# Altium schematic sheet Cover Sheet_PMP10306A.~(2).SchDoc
size 431 x 279 mm; Date: Not shown in title block; ApprovedBy: Not shown in title block; CheckedBy: Not shown in title block; Author: Not shown in title block; CompanyName: Not shown in title block; Engineer: Not shown in title block; Organization: Not shown in title block; Address1: Not shown in title block; Address2: Not shown in title block; Address3: Not shown in title block; Address4: Not shown in title block; DocumentNumber: 1; Revision: Use project parameter SCH_Rev; SheetNumber: 1; SheetTotal: 1; PageSetup: Record=PageOptions|CenterHorizontal=True|CenterVertical=True|PrintScale=1.00|XCorrection=1.00|YCorrection=1.00|PrintKind=0|BorderSize=5000000|LeftOffset=0|BottomOffset=0|Orientation=2|PaperLength=1000|PaperWidth=1000|Scale=100|PaperSource=15|PrintQuality=600|MediaType=1|DitherType=10|PaperKind=Letter|PrintScaleMode=1
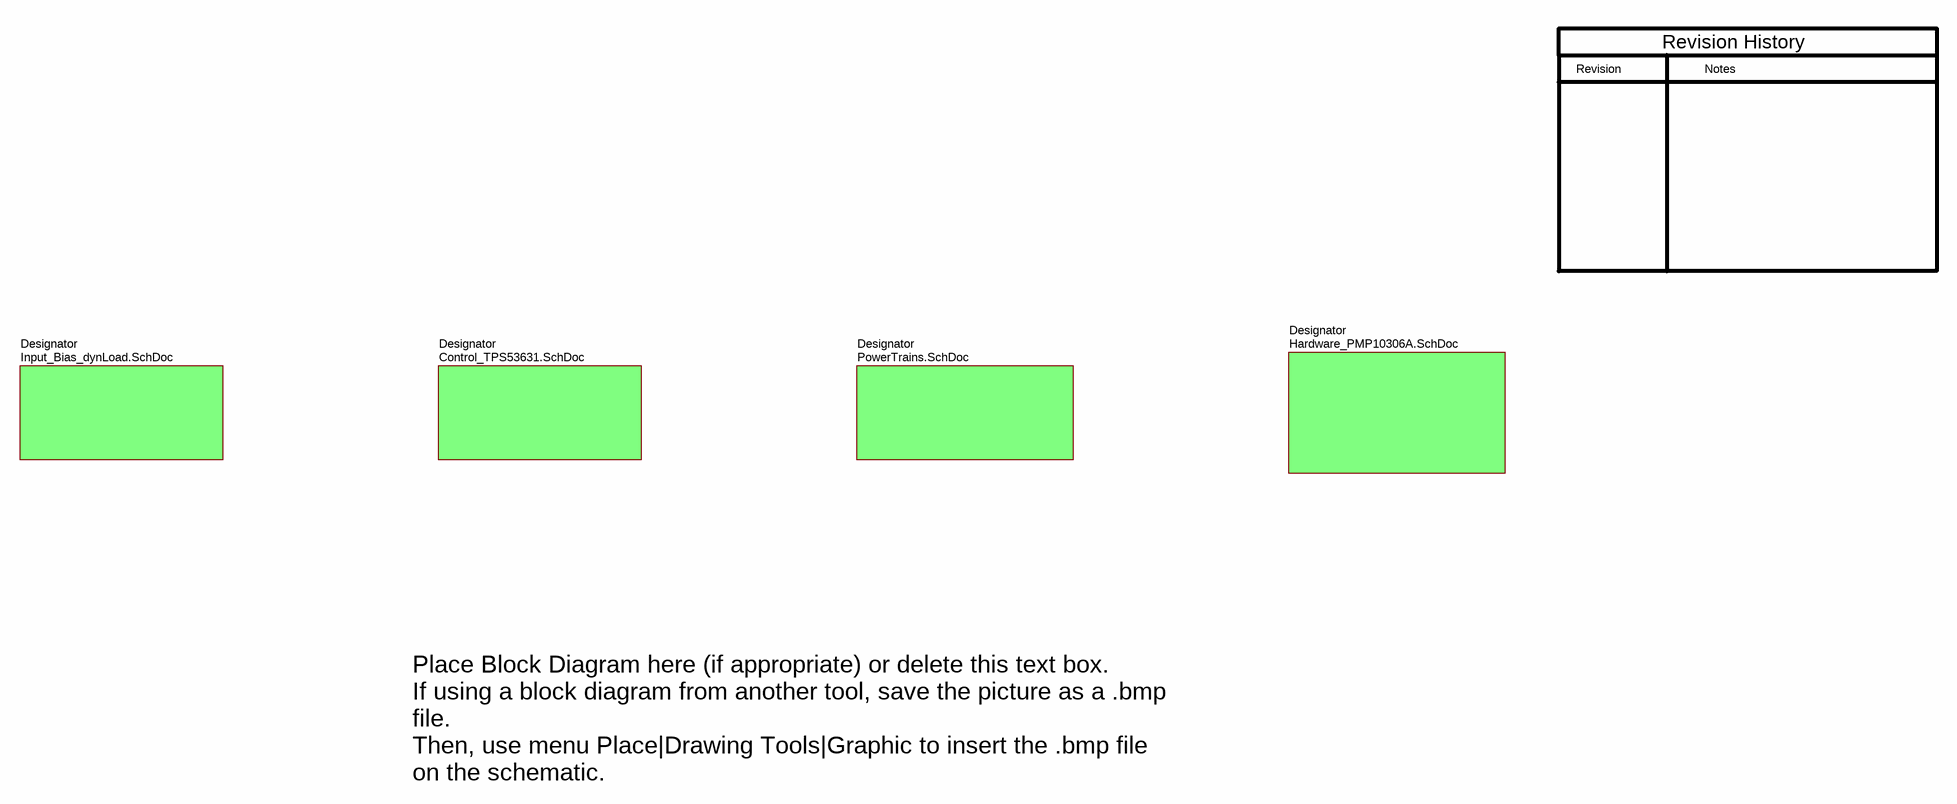
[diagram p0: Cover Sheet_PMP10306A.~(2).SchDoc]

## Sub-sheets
Designator = Input_Bias_dynLoad.SchDoc: no entries
Designator = Control_TPS53631.SchDoc: no entries
Designator = PowerTrains.SchDoc: no entries
Designator = Hardware_PMP10306A.SchDoc: no entries

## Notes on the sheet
- Revision
- Notes
- Revision History
- Place Block Diagram here (if appropriate) or delete this text box.
  If using a block diagram from another tool, save the picture as a .bmp file.
  Then, use menu Place|Drawing Tools|Graphic to insert the .bmp file on the schematic.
